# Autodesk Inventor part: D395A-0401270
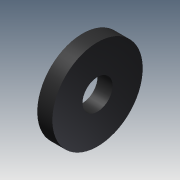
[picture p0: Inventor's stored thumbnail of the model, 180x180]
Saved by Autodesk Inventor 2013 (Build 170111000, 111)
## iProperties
Shininess: 69.0
Length Units: 11269
Angle Units: 11279
Time Units: 11290
Mass Units: 11283
Length Display Precision: 3
Angle Display Precision: 2
Created: 2002-06
Part Number: D395A-0401270
Material: Rubber
Document SubType Name: Modeling
Designer: LAlexey
Density: 0.93 g/cm^3
Mass: 2.92168 g
Surface Area: 18.8496 cm^2
Volume: 3.14159 cm^3
Density: 1.06
Volumn: 3.8900771033075623
Area: 34.55751918948772
PropertySet Name: Model Information
Control State: 0
Master: False
Checked Out: True
Author: LAlexey
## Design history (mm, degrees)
body "Solid1"
revolve "Revolution1" stored, may be unused: angle "d6" = 90 deg
sketch "Sketch1"
  geometry: L1 (0.27, 31.748)-(0.27, 41.748); L2 (0.27, 41.748)-(5.27, 41.748); L3 (5.27, 41.748)-(5.27, 31.748); L4 (5.27, 31.748)-(0.27, 31.748); L5 (6.357, 26.748)-(8.857, 26.748)
  constraints: 10 end point, 2 parallel, 1 vertical
  dimensions: "d1" = 5 distance between parallel lines of L5 L4; "d4" = 5 distance between parallel lines of L3 L1; "d5" = 15 distance between parallel lines of L5 L2
